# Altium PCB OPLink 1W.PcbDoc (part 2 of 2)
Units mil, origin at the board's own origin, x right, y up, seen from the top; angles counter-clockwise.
Board outline 1023.62 x 1417.32 mil, 4 copper layers (Top Layer, PWR Layer, GND Layer, Bottom Layer), stack 89.2 mil thick; 64 components, 74 nets, 299 pads, 144 vias.
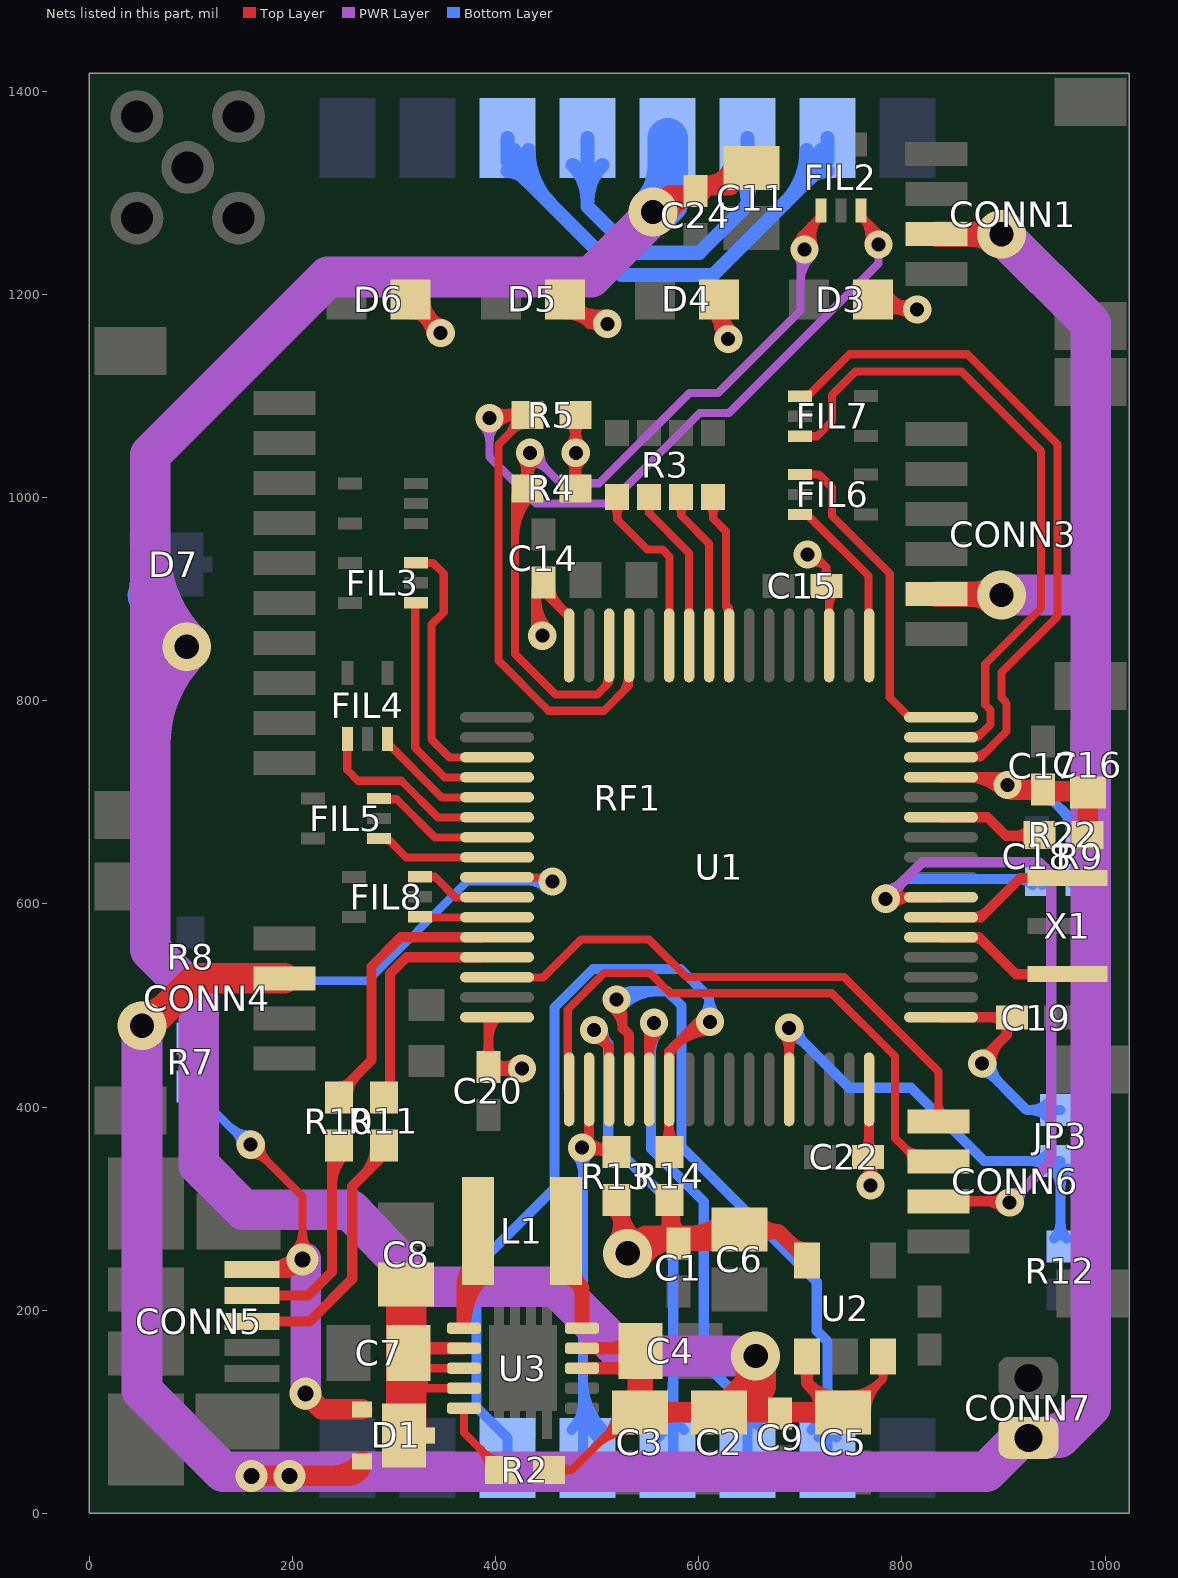
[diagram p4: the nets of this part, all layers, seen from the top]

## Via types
v1: diameter 27.8, hole 13.78, Top Layer to Bottom Layer, tented both sides, 127 vias
v2: diameter 48, hole 24, Top Layer to Bottom Layer, tented both sides, 8 vias
v3: diameter 31.5, hole 15.75, Top Layer to Bottom Layer, tented both sides, 4 vias
v4: diameter 25.98, hole 12, Top Layer to Bottom Layer, tented bottom, 4 vias
v5: diameter 26, hole 12, Top Layer to Bottom Layer, tented bottom, 1 vias

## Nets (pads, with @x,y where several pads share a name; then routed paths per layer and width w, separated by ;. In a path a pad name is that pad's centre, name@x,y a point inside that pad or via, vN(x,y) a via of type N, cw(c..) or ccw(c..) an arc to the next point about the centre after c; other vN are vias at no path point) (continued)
NetFIL2_1: FIL2.1 R4.1 U1.30 | length 1222
  Top Layer w8: 419,960.26 cw(c478.15,960.26) R4.1@436.32,1002.08 ; 419,979.57 cw(c458.84,979.57) R4.1@430.67,1007.74 ; R4.1@419,998.89 cw(c439.52,998.89) R4.1@425.01,1013.4 ; R4.1@424.46,1015.92 ccw(c407.77,1032.61) 431.38,1032.61 ccw(c454.99,1032.61) R4.1@438.29,1015.92 ; v1@425.7,1038.61 cw(c407.81,1027.02) R4.1@428.4,1021.5 ; v1@427,1037 cw(c416.44,1026.44) 431.38,1026.44 ; R4.1@428.48,1021.78 cw(c450.19,1015.96) v1@438.95,1035.43 ; R4.1@430.5,1007.5 419,996 419,846 458.91,806.09 500.09,806.09 511.73,817.73 U1.30@511.73,854.5 ; R4.1@431.38,1009 431.38,1041.38 v1(434,1044) ; R4.1@431.38,1013.78 cw(c464.22,1013.78) v1@441,1037 ; 505.72,811.72 ccw(c494.13,823.3) U1.30@510.52,823.3 ; v1@698.23,1242.02 cw(c713.97,1247.43) 702.2,1259.2 ; v1@699.11,1252.61 ccw(c694.35,1261) 704,1261 ; v1(704,1244) 704,1261 ; v1@705.79,1244.62 cw(c727.45,1252.06) 711.26,1268.26 ; v1@708.89,1252.61 cw(c713.65,1261) 704,1261 ; v1@713.36,1247.22 cw(c740.93,1256.7) FIL2.1@720.31,1277.31 ; FIL2.1@715.87,1272.87 cw(c720.32,1268.42) FIL2.1@720.32,1274.71 ; FIL2.1@720.32,1282.52 FIL2.1@720.32,1277.32 ; 704,1261 FIL2.1@720.32,1277.32
  PWR Layer w8: v1@434,1034.1 cw(c434,1010.21) 450.9,1027.1 cw(c467.79,1044) v1@443.9,1044 ; v1(434,1044) 464,1014 502,1014 591,1103 619,1103 700,1184 700,1249 v1@699,1250 ; v1@697,1237 cw(c689.76,1229.76) 700,1229.76 cw(c718.24,1229.76) v1@705.34,1242.66 ; 700,1210.45 cw(c737.55,1210.45) v1@711,1237
NetFIL2_3: FIL2.3 R5.1 U1.29 | length 1343
  Top Layer w8: v1(394,1078) 397,1081 R5.1@431.38,1081 ; v1@398.99,1086.55 ccw(c411.11,1107.34) R5.1@417.34,1084.09 ; v1@401,1071 cw(c425.14,1046.86) R5.1@425.14,1081 ; v1@401,1085 ccw(c410.65,1094.65) 410.65,1081 ; v1@402.57,1073.05 cw(c422.8,1061.37) R5.1@416.76,1083.94 ; 410.88,1059.88 ccw(c389.77,1081) R5.1@419.63,1081 ; 417.14,1066.14 cw(c429.41,1053.87) R5.1@429.41,1071.22 ; R5.1@422.49,1074.08 ccw(c405.8,1057.39) 405.8,1081 ccw(c405.8,1104.61) R5.1@422.49,1087.92 ; R5.1@431,1080 403,1052 403,839.37 452.29,790.09 506.71,790.09 531.42,814.79 U1.29@531.42,854.5 ; 523.32,806.69 ccw(c506.71,823.3) U1.29@530.2,823.3 ; FIL2.3@759.68,1274.71 cw(c759.68,1268.42) FIL2.3@764.13,1272.87 ; FIL2.3@759.68,1282.52 FIL2.3@759.68,1277.32 ; v1@767.33,1251.13 ccw(c739.61,1257.24) FIL2.3@759.69,1277.31 ; 770.01,1266.99 cw(c756.53,1253.51) v1@775.15,1249.41 ; v1(777,1249) 777,1260 FIL2.3@759.68,1277.32
  PWR Layer w8: v1@387,1071 cw(c370.11,1054.11) 394,1054.11 cw(c417.89,1054.11) v1@401,1071 ; v1(394,1078) 394,1040 440,994 512,994 601,1083 629.72,1083 777,1230.28 777,1239 v1@783,1245
NetFIL6_1: FIL6.1 U1.16 | length 325.9
  Top Layer w8: FIL6.1@699.52,1022.68 718.32,1022.68 731,1010 731,982 788,925 788,803 807.36,783.64 U1.16@838.5,783.64
NetFIL6_3: FIL6.3 U1.17 | length 161.2
  Top Layer w8: FIL6.3@699.52,983.32 706.68,983.32 767,923 767,855.14 U1.17@767.64,854.5
NetFIL7_1: FIL7.1 U1.14 | length 709.4
  Top Layer w8: FIL7.1@699.52,1099.68 707.17,1099.68 748.48,1141 864.38,1141 953,1052.38 953,883 898,828 898,803 902,799 ; FIL7.1@705.82,1101.2 ccw(c705.82,1108.1) FIL7.1@710.7,1103.22 ; U1.14@838.5,744.27 877.31,744.27 903,769.96 903,797 ; U1.14@869.7,745.48 ccw(c869.7,766.78) 884.76,751.72
NetFIL7_3: FIL7.3 U1.15 | length 670.3
  Top Layer w8: FIL7.3@699.52,1060.32 716.32,1060.32 731,1075 731,1100.89 754.11,1124 858.75,1124 937,1045.75 937,891 882,836 882,796 887,791 887,776.59 874.37,763.95 U1.15@838.5,763.95 ; U1.15@869.7,765.17 ccw(c869.7,779.36) 879.74,769.33
NetJP3_1: JP3.1 R12.1 U1.60 | length 637.5
  Top Layer w10: v1@682.71,471.71 cw(c667.52,456.52) 689,456.52 cw(c710.48,456.52) v1@695.29,471.71 ; U1.60@688.9,417.5 689,417.6 v1(689,478)
  Bottom Layer w10: v1@689,469.1 cw(c689,447.62) 704.19,462.81 cw(c719.38,478) v1@697.9,478 ; v1(689,478) 748,419 809,419 881,347 JP3.1@956,347 R12.1@956,273.62 ; JP3.1@944.15,339.4 ccw(c925.8,321.05) 925.8,347 ccw(c925.8,372.95) JP3.1@944.15,354.6 ; JP3.1@948.4,339.4 cw(c930.05,321.05) 956,321.05 cw(c981.95,321.05) JP3.1@963.6,339.4 ; R12.1@949.79,270.8 ccw(c934.8,285.79) 956,285.79 ccw(c977.2,285.79) R12.1@962.21,270.8
NetL1_1: L1.1 U3.1 | length 151.4
  Top Layer w15: U3.1@368.93,185 368.93,223.93 ; U3.1@368.93,187.46 cw(c435.83,187.46) L1.1@388.53,234.77 ; 368.93,223.67 cw(c399.62,223.67) L1.1@377.92,245.37 ; L1.1@374.49,239.71 cw(c355.23,237.63) 368.93,223.93 ; L1.1@382,237 368.93,223.93
NetL1_2: L1.2 U3.10 | length 99.7
  Top Layer w15: L1.2@469.16,232.35 cw(c468.88,216.16) 485.07,216.16 ; L1.2@473,234 485.07,221.93 ; L1.2@477.55,240.47 ccw(c503.22,240.08) 485.07,221.93 ; U3.10@485.07,185 485.07,221.93
NetR3_1: R3.1 U1.27 | length 206
  Top Layer w8: R3.1@514.23,994 cw(c500.9,980.66) 519.76,980.66 cw(c538.61,980.66) R3.1@525.28,994 ; R3.1@519.76,1000.5 519.76,978.24 549.28,948.72 564.28,948.72 571.31,941.69 571.31,855.02 U1.27@570.79,854.5
NetR3_2: R3.2 U1.26 | length 181.8
  Top Layer w8: R3.2@546.85,993.06 cw(c541.19,984.75) 551.25,984.75 ; R3.2@551.25,1000.5 551.25,984.75 ; R3.2@555.65,993.06 ccw(c561.31,984.75) 551.25,984.75 ; U1.26@590.47,854.5 590.47,945.53 551.25,984.75
NetR3_3: R3.3 U1.25 | length 183.1
  Top Layer w8: R3.3@577.59,993.65 cw(c567.57,982.25) 582.75,982.25 ; R3.3@582.75,1000.5 582.75,982.25 ; R3.3@587.91,993.65 ccw(c597.93,982.25) 582.75,982.25 ; U1.25@610.16,854.5 610.16,954.84 582.75,982.25
NetR3_4: R3.4 U1.24 | length 209
  Top Layer w8: R3.4@608.72,994 cw(c595.39,980.66) 614.24,980.66 cw(c633.1,980.66) R3.4@619.77,994 ; R3.4@614.24,1000.5 614.24,979.38 627,966.63 627,894 ; 627,895.5 ccw(c639.64,895.5) U1.24@630.7,886.56 ; U1.24@628.7,886.13 ccw(c621.74,888.74) 627,894 ; U1.24@629.84,854.5 629.84,891.16 627,894 ; U1.24@630.59,886.67 cw(c636.29,894) 627,894
NetR13_1: R13.1 RF1.13 U1.50 | length 654.2
  Top Layer w10: v1@485,355 v1@490,360 ; v1(485,360) v1@490,360 ; v1@491.2,353.62 cw(c500.3,344.27) 503.67,356.87 ; v1@491.29,353.71 cw(c506.48,338.52) 506.48,360 cw(c506.48,381.48) v1@491.29,366.29 ; v1@491.99,360 cw(c491.99,330.58) R13.1@512.79,351.38 ; U1.50@492.05,417.5 492.05,362.05 v1@490,360 ; v1@492.71,364.45 ccw(c505.96,372.1) 502,357.32 ; 503.62,360 ccw(c503.62,372.97) R13.1@512.79,363.8 ; R13.1@516.64,355.62 512.27,360 v1@490,360
  Bottom Layer w10: RF1.13@474.68,82.16 ccw(c447.35,109.49) 486,109.49 ; v1@478.71,353.71 cw(c461.11,336.11) 486,336.11 ; 486,107.7 ccw(c532.13,107.7) RF1.13@499.51,75.09 ; 486,131.84 ccw(c556.27,131.84) RF1.13@506.58,82.16 ; 486,340.93 cw(c504.07,340.93) v1@491.29,353.71 ; v1@486,357 486,54.39 RF1.13@490.63,54.39
NetR14_1: R14.1 RF1.14 U1.54 | length 979.4
  Top Layer w10: R14.1@564.79,363.8 ccw(c550.32,378.27) 570.79,378.27 ; 570.79,379.3 ccw(c592.71,379.3) R14.1@577.21,363.8 ; R14.1@571,355.62 570.79,355.83 U1.54@570.79,417.5 570.79,454.79 600,484 v1(611,484) ; U1.54@571,448.7 cw(c586.23,448.7) 575.46,459.46 ; 577.03,461.03 cw(c611,427.07) v1@611,475.1 ; 594.1,478.1 cw(c611,461.21) v1@611,485.1
  Bottom Layer w10: RF1.14@411.89,54.39 411.89,74.11 381.32,104.67 381.32,243.32 458,320 458,498 496,536 582,536 610,508 610,484 v1(611,484) ; v1@604.71,490.29 ccw(c591.93,503.07) 610,503.07 ; 610,507.89 ccw(c634.89,507.89) v1@617.29,490.29
NetR22_2: R22.2 U1.11 | length 142.3
  Top Layer w10: U1.11@838.5,685.21 884.22,685.21 902.43,667 R22.2@940,667 ; 909.8,667 ccw(c909.8,691.61) R22.2@927.2,674.21 ; 914.63,667 cw(c914.63,649.22) R22.2@927.2,661.79
NetRF1_3: RF1.3 RF1.7 | length 672.3
  Bottom Layer w14: RF1.3@411.89,1321.24 cw(c411.89,1297.4) RF1.3@428.75,1314.25 ; RF1.3@411.89,1353.61 411.89,1331.11 524,1219 614,1219 726.85,1331.85 RF1.7@726.85,1353.61 ; RF1.3@418.45,1341.8 ccw(c460.08,1341.8) 430.64,1312.36 ; RF1.3@432.45,1341.8 ccw(c507.88,1341.8) 454.54,1288.46 ; 684.72,1289.72 ccw(c632.65,1341.8) RF1.7@706.29,1341.8 ; 708.62,1313.62 ccw(c680.45,1341.8) RF1.7@720.29,1341.8 ; 708.73,1313.73 cw(c726.85,1295.61) RF1.7@726.85,1321.24
NetRF1_4: RF1.4 RF1.6 | length 484.3
  Bottom Layer w14: RF1.4@476.09,1327.26 cw(c441,1292.16) 490.63,1292.16 cw(c540.26,1292.16) RF1.4@505.17,1327.26 ; RF1.4@490.63,1353.61 490.63,1286.48 536.11,1241 600.89,1241 648.11,1288.22 RF1.6@648.11,1353.61 ; RF1.6@633.57,1327.26 cw(c598.48,1292.16) 648.11,1292.16 cw(c697.74,1292.16) RF1.6@662.65,1327.26
NetRF1_10: RF1.10 U1.52 | length 901
  Top Layer w10: v1@513.89,498.71 cw(c498.93,477.37) 525,477.37 ; v1@518.28,497.13 cw(c517.69,489.84) 525,489.84 ; v1(519,506) 519,497 525,491 525,478 531.42,471.58 U1.52@531.42,417.5
  Bottom Layer w10: v1@518.22,506.78 cw(c535.65,489.35) 535.65,514 ; v1@524.15,513.25 ccw(c528.13,518.86) 533,514 ; v1@525.29,499.71 cw(c559.79,465.21) 559.79,514 ; v1@526,507 533,514 ; RF1.10@710.9,82.16 ccw(c672.39,120.67) 726.85,120.67 ccw(c781.31,120.67) RF1.10@742.8,82.16 ; RF1.10@717.97,75.09 ccw(c696.53,96.52) 726.85,96.52 ccw(c757.17,96.52) RF1.10@735.73,75.09 ; RF1.10@726.85,54.39 726.85,169.11 716.1,179.86 716.1,227.9 583,361 583,500 569,514 533,514
NetRF1_11: RF1.11 U1.53 | length 641.1
  Top Layer w10: U1.53@551.1,417.5 551.1,478.1 v1(556,483) ; U1.53@551.1,449.7 cw(c589.3,449.7) v1@562.29,476.71
  Bottom Layer w10: v1@549.71,476.71 cw(c541.76,468.76) 553,468.76 ; 553,454.28 cw(c584.72,454.28) v1@562.29,476.71 ; v1@553,476 553,359 605,307 605,149 648.11,105.89 ; RF1.11@636.57,85.59 ccw(c624.49,105.89) 648.11,105.89 ; RF1.11@648.11,54.39 648.11,105.89 ; RF1.11@659.65,85.59 cw(c671.73,105.89) 648.11,105.89
NetRF1_12: RF1.12 U1.51 | length 705.2
  Top Layer w10: v1@497,467.1 cw(c497,450.45) 508.77,462.23 ; v1@502,478 502,469 511.73,459.27 ; v1@505.87,475.27 ccw(c526.06,473.59) 511.73,459.27 ; U1.51@511.73,417.5 511.73,459.27
  Bottom Layer w10: v1@497.53,467.12 cw(c498.57,449.57) 511,462 ; v1@502,478 502,471 511,462 ; v1@505.88,475.47 ccw(c523.43,474.43) 511,462 ; RF1.12@553.42,82.16 ccw(c501.56,134.01) 574.9,134.01 ; RF1.12@560.49,75.09 ccw(c525.71,109.87) 574.9,109.87 ; RF1.12@569.37,54.39 574.9,59.92 574.9,303.1 511,367 511,462 ; 574.9,107.32 ccw(c610.49,107.32) RF1.12@585.32,82.16
  other v1: 497,476
NRST: C18.2 CONN6.2 R9.1 U1.7 | length 1126.1
  Top Layer w10: v1(784,605) 785.47,606.47 U1.7@838.5,606.47 ; v1@790.29,598.71 cw(c809.04,579.96) U1.7@809.04,606.47 ; v1@790.29,611.29 ccw(c801.93,622.93) 801.93,606.47 ; CONN6.2@835.9,307.32 904.68,307.32 v1(906,306) ; CONN6.2@859.41,302.5 cw(c871.04,290.87) 871.04,307.32 cw(c871.04,323.76) CONN6.2@859.41,312.13 ; 881.34,307.32 cw(c881.34,281.34) v1@899.71,299.71 ; 887.69,307.32 ccw(c887.69,324.31) v1@899.71,312.29
  PWR Layer w10: v1(784,605) 820,641 935,641 946.9,629.1 946.9,346.9 v1(906,306) ; v1@784,613.9 ccw(c784,635.38) 799.19,620.19 ccw(c814.38,605) v1@792.9,605 ; v1@906,314.9 ccw(c906,336.38) 921.19,321.19 ccw(c936.38,306) v1@914.9,306
  Bottom Layer w10: v1(784,605) 803.38,624.38 R9.1@974,624.38 ; v1@784,613.9 ccw(c784,635.38) 799.19,620.19 ccw(c814.38,605) v1@792.9,605 ; 914.14,624.38 cw(c914.14,604.52) C18.2@928.18,618.56 ; 918.97,624.38 ccw(c918.97,637.41) C18.2@928.18,628.19 ; C18.2@937.82,618.56 cw(c951.86,604.52) 951.86,624.38 ; C18.2@937.82,628.19 ccw(c947.03,637.41) 947.03,624.38 ; 951.47,624.38 ccw(c951.47,648.88) R9.1@968.79,631.55 ; 956.14,624.38 cw(c956.14,606.49) R9.1@968.79,619.14
OSC_IN: U1.5 X1.1 | length 153.7
  Top Layer w10: U1.5@838.5,567.1 875.9,567.1 912.24,530.76 X1.1@965,530.76 ; U1.5@869.7,566.89 cw(c869.7,551.41) 880.65,562.35
OSC_OUT: U1.6 X1.2 | length 158.2
  Top Layer w10: U1.6@838.5,586.79 877.79,586.79 916.24,625.24 X1.2@965,625.24 ; U1.6@869.7,587 ccw(c869.7,607.04) 883.87,592.87
PG: R2.2 U3.5 | length 112.8
  Top Layer w8: U3.5@368.93,103.63 368.93,79.45 R2.2@405.38,43 ; 385.32,63.06 cw(c365.27,43) R2.2@393.63,43 ; 390.08,58.3 ccw(c403.41,71.64) R2.2@403.41,52.78
S1_IN: FIL3.3 U1.35 | length 271.8
  Top Layer w8: FIL3.3@321.48,935.68 338.32,935.68 349,925 349,887 337,875 337,762 354.73,744.27 U1.35@401.5,744.27
S2_IN: FIL3.1 U1.36 | length 233.9
  Top Layer w8: FIL3.1@321,895 321,753.63 350.04,724.58 U1.36@401.5,724.58
S3_IN: FIL4.3 U1.37 | length 137
  Top Layer w8: FIL4.3@293.5,758.5 347.1,704.9 U1.37@401.5,704.9 ; FIL4.3@293.68,754.71 cw(c293.68,746) 299.84,752.16
S4_IN: FIL4.1 U1.38 | length 192.7
  Top Layer w8: FIL4.1@254,757.83 254,732 264.8,721.2 307.2,721.2 343.19,685.21 U1.38@401.5,685.21
S5_IN: FIL5.3 U1.39 | length 137
  Top Layer w8: FIL5.3@280,703 302.77,703 340.25,665.53 U1.39@401.5,665.53
S6_IN: FIL5.1 U1.40 | length 129.3
  Top Layer w8: FIL5.1@287,666 292,666 312.16,645.84 U1.40@401.5,645.84 ; FIL5.1@291.78,662.8 cw(c291.78,654.55) 297.61,660.39
SWDCLK: CONN6.3 U1.49 | length 617.8
  Top Layer w8: 471.1,454.68 ccw(c478.34,454.68) U1.49@473.22,449.56 ; U1.49@472.36,417.5 471.1,418.76 471.1,496.1 506.9,531.9 552.1,531.9 572,512 731,512 793,450 793,369.66 815.97,346.68 CONN6.3@835.9,346.68 ; 801.78,360.88 ccw(c817.2,376.3) CONN6.3@817.2,354.5 ; 804.73,357.93 cw(c793.48,346.68) CONN6.3@809.39,346.68
SWDIO: CONN6.4 U1.46 | length 582.3
  Top Layer w8: U1.46@401.5,527.73 446.73,527.73 484,565 551,565 588,528 743,528 835.9,435.1 CONN6.4@835.9,386.06 ; CONN6.4@830.37,391.58 ccw(c817.04,404.91) 835.9,404.91 ccw(c854.76,404.91) CONN6.4@841.42,391.58
TO_REG: C7.1 C8.1 D1.3 U3.2 U3.3 U3.4 | length 326.1
  Top Layer w8: C7.1@314.53,158 C7.1@329.53,143 ; U3.4@368.93,123.32 329.53,123.32 C7.1@329.53,143 ; U3.3@368.93,143 C7.1@329.53,143
  Top Layer w12: C7.1@312,163 312.31,162.68 U3.2@368.93,162.68
  Top Layer w40: D1.3@310,77 312,79 312,163 C8.1@312,225.47
UART1_RX: FIL8.1 U1.43 | length 76.2
  Top Layer w8: FIL8.1@325.48,587.32 326.01,586.79 U1.43@401.5,586.79
UART1_TX: FIL8.3 U1.42 | length 84.4
  Top Layer w8: FIL8.3@325.48,626.68 340.32,626.68 360.53,606.47 U1.42@401.5,606.47
USB_D_N: R10.1 U1.44 | length 294.8
  Top Layer w10: R10.1@245,411 247,413 247,415 278,446 278,538.46 306.65,567.1 U1.44@386.5,567.1 ; R10.1@246,420.37 ccw(c246,435.75) R10.1@256.87,424.87 ; R10.1@254.78,411.59 cw(c281.79,411.59) 262.69,430.69
USB_D_P: R11.1 U1.45 | length 221.3
  Top Layer w10: R11.1@296,407 296,531 312.42,547.42 U1.45@386.5,547.42
USB_PWR: CONN5.1 D1.2 R7.1 | length 682.6
  Top Layer w8: v1@159,353.1 cw(c159,329.21) 175.9,346.1 cw(c192.79,363) v1@168.9,363 ; v1(159,363) 210,312 v3(210,250) ; v3@201.69,258.31 ccw(c181.64,278.36) 210,278.36 ccw(c238.36,278.36) v3@218.31,258.31
  Top Layer w17: CONN5.1@160.33,240.18 195.18,240.18 ; CONN5.1@179.13,240.05 ccw(c179.13,278.47) v3@206.3,251.3 ; 190.56,242.22 cw(c200,225.88) v3@207.22,243.3 ; v3@207.5,252.5 195.18,240.18 ; v3@207.7,243.13 ccw(c203.82,231.54) 195.18,240.18
  Top Layer w20: v3(213,118) 228.41,102.59 D1.2@268.66,102.59
  PWR Layer w30: v3@213,117 v3(213,118) v3@213,251
  Bottom Layer w8: R7.1@100,408.63 cw(c100,383.59) 117.7,401.3 ; R7.1@109.78,418.41 ccw(c131.96,418.41) 116.28,402.72 ; R7.1@110,423.38 110,409 156,363 v1(159,363) ; 136.98,382.02 ccw(c159,404.04) v1@159,372.9 ; 144.23,374.77 cw(c132.45,363) v1@149.1,363
USB_R_N: CONN5.2 R10.2 | length 258.2
  Top Layer w10: CONN5.2@160.33,214.59 215.59,214.59 239,238 R10.2@239,356 ; 239,322.31 cw(c284.1,322.31) R10.2@252.21,354.2 ; 239,346.46 cw(c259.95,346.46) R10.2@245.14,361.27
USB_R_P: CONN5.3 R11.2 | length 292.8
  Top Layer w10: CONN5.3@160.33,189 217,189 259,231 259,322 296.5,359.5 R11.2@296.5,361.5 ; 269.77,332.77 ccw(c242.14,360.41) R11.2@281.22,360.41
VBUS_SEN: R7.2 R8.2 U1.41 | length 659.4
  Top Layer w8: U1.41@401.5,626.16 451.84,626.16 v1(456,622)
  Bottom Layer w8: R7.2@93.08,476.51 ccw(c76.39,493.2) 100,493.2 ccw(c123.61,493.2) R7.2@106.92,476.51 ; R8.2@93.08,515.49 cw(c76.39,498.8) 100,498.8 cw(c123.61,498.8) R8.2@106.92,515.49 ; R8.2@106.92,517.46 cw(c123.61,500.77) 123.61,524.38 cw(c123.61,547.99) R8.2@106.92,531.29 ; R7.2@110,470.62 100,480.62 R8.2@100,524.38 274.38,524.38 372,622 v1(456,622) ; v1@449,615 ccw(c432.11,598.11) 432.11,622 ccw(c432.11,645.89) v1@449,629
VCC: C1.1 C6.1 C14.1 C15.2 C16.2 C17.1 C19.2 C20.1 C22.1 D3.2 D4.2 D5.2 D6.2 JP3.2 R4.2 R5.2 R9.2 R13.2 R14.2 R22.1 U1.1 U1.13 U1.19 U1.32 U1.48 U1.64 U2.5 | length 3229
  Top Layer w8: v1(707,944) 713,944 725.62,931.38 ; v1@710.42,934.71 cw(c715.42,921.17) 725.62,931.38 ; v1@716.9,944 ccw(c726.31,944) 719.65,937.35 ; C15.2@720.2,918.62 ccw(c707.91,931.38) 725.62,931.38 ; C15.2@724.04,907.48 cw(c713.82,897.26) 728.27,897.26 ; C15.2@725.62,913 725.62,931.38 ; U1.19@728.27,854.5 C15.2@728.27,913 ; 728.27,891.02 cw(c751.53,891.02) C15.2@735.08,907.48 ; C15.2@731.04,918.62 cw(c743.33,931.38) 725.62,931.38
  Top Layer w10: D6.2@316.5,1180.31 cw(c316.5,1144.86) 341.56,1169.93 cw(c366.63,1195) D6.2@331.18,1195 ; D6.2@316.5,1195 v1@348.75,1162.75 ; D6.2@323.35,1180.45 cw(c309.06,1155.7) v1@337.23,1160.5 ; D6.2@328.34,1183.16 cw(c307.18,1162) v1@337.1,1162 ; D6.2@335.22,1180.93 cw(c316.25,1169.97) v1@337.41,1164.3 ; D6.2@335.52,1180.4 ccw(c353.75,1190.93) v1@348.3,1170.59 ; 336.78,1174.72 ccw(c346,1183.94) v1@346,1170.9 ; C20.1@388.18,448.38 ccw(c376.56,460) 393,460 ccw(c409.44,460) C20.1@397.82,448.38 ; C20.1@393,439.62 U1.48@393,488 ; 393,467.33 cw(c422.53,467.33) U1.48@401.65,488.21 ; v1@440,860 440,909.38 C14.1@447,916.38 447,908.59 472.36,883.23 U1.32@472.36,854.5 ; 440,899.97 ccw(c481.97,899.97) v1@452.29,870.29 ; C14.1@453.81,912.44 ccw(c479.55,912.44) 461.35,894.24 ; D5.2@468.62,1180.32 cw(c469.62,1148.46) 492.16,1171 ; R4.2@472.41,1015.21 ccw(c457.43,1030.2) 478.62,1030.2 ccw(c499.82,1030.2) R4.2@484.83,1015.21 ; R5.2@472.41,1074.79 cw(c457.43,1059.8) 478.62,1059.8 cw(c499.82,1059.8) R5.2@484.83,1074.79 ; v1@472.71,1037.71 cw(c458.43,1023.43) 478.62,1023.43 ; v1@472.71,1050.29 ccw(c458.43,1064.57) 478.62,1064.57 ; v1@473.33,1037.14 cw(c465.8,1028.03) 477.22,1024.97 ; 478.54,1029.9 cw(c488.71,1027.18) v1@483.45,1036.29 ; R4.2@478.62,1009 R5.2@478.62,1081 ; R4.2@478.62,1021.61 cw(c501.39,1021.61) v1@485.29,1037.71 ; 478.62,1066.39 ccw(c501.39,1066.39) v1@485.29,1050.29 ; 479.7,1026.19 cw(c488.68,1028.59) v1@483.73,1036.47 ; D5.2@482.84,1194.54 ccw(c514.7,1193.54) 492.16,1171 ; D5.2@483.47,1179.7 ccw(c507.38,1203.6) v1@510.09,1169.9 ; v1@502.89,1165.65 ccw(c492.16,1157.57) 492.16,1171 ; v1@502.89,1176.35 cw(c492.16,1184.43) 492.16,1171 ; v1@509.29,1179.87 cw(c505.1,1231.93) D5.2@468.16,1195 492.16,1171 ; v1(510,1171) 492.16,1171 ; R13.2@512.79,300.2 cw(c480.91,268.31) v2@526,268.31 ; v2@514.86,267.47 ccw(c492.21,284.64) 519.66,291.99 ccw(c545.22,298.84) v2@536.36,273.9 ; v2@516.56,269.44 ccw(c493.79,292.21) 526,292.21 ; R13.2@519,308.38 526,301.38 v2@526,262 ; R13.2@519.86,307.27 cw(c505.05,292.46) 526,292.46 ; 526,281.65 ccw(c548.8,281.65) v2@535.32,263.26 ; R13.2@526,301.38 ccw(c563.26,301.38) v2@541.23,271.32 ; D4.2@611.6,1182.84 cw(c600.87,1167) 620,1167 ; D4.2@617.38,1176.78 ccw(c633.36,1181.06) v1@630.52,1164.77 ; D4.2@619.83,1195 D4.2@620,1194.83 ; 620,1173.13 ccw(c643.64,1173.13) v1@628.28,1155.16 ; v1@621.09,1160.07 ccw(c615.79,1162.79) 620,1167 ; v1@627.34,1164.74 cw(c625.8,1172.8) 620,1167 ; D4.2@628.29,1183 ccw(c639.58,1167) 620,1167 ; v1@632,1155 620,1167 ; v1@634.78,1162.77 cw(c662.17,1194.83) D4.2@620,1194.83 ; C22.1@761.81,355.82 ccw(c747.73,369.9) 767.64,369.9 ; v1@762.71,329.29 ccw(c747.52,344.48) 769,344.48 ccw(c790.48,344.48) v1@775.29,329.29 ; v1@765.02,330.96 ccw(c759.85,341.29) 771.01,338.3 ccw(c778.05,336.42) v1@773.97,330.38 ; C22.1@765.74,346.18 cw(c757.88,338.32) 769,338.32 ; 767.64,364.99 ccw(c780.61,364.99) C22.1@771.44,355.82 ; U1.64@767.64,417.5 767.64,356.98 769.62,355 769,354.38 v1(769,323) ; v1@769,330.79 cw(c790.77,330.79) C22.1@775.38,346.18 ; D3.2@771.5,1195 781.5,1185 v1(815,1185) cw(c815,1220.99) D3.2@784.1,1202.53 ; D3.2@775.52,1197.4 ccw(c797.38,1210.46) 797.38,1185 ; v1@806.87,1181.39 ccw(c793.11,1175.28) 797,1189.82 ccw(c800.9,1204.36) v1@809.76,1192.19 ; v1@808.71,1178.71 ccw(c793.52,1163.52) 793.52,1185 ccw(c793.52,1206.48) v1@808.71,1191.29 ; U1.1@838.5,488.36 911.74,488.36 913.38,490 906.1,490 903.1,487 903.1,471.1 884,452 v1@884,445 ; U1.13@838.5,724.58 900.42,724.58 v1@903.38,721.62 ; U1.13@864.21,724.58 cw(c864.21,677.21) v1@897.71,710.71 ; v1@879,451.9 ccw(c879,463.72) 887.36,455.36 ; 887.12,488.36 cw(c887.12,470.68) 899.62,483.18 cw(c891.23,474.79) 903.1,474.79 ; v1@887.9,443 cw(c919.04,443) 897.02,465.02 ; 888.36,724.58 cw(c888.36,701.36) v1@904.78,717.78 ; 888.87,488.36 ccw(c888.87,503.57) C19.2@899.62,492.82 ; 903.1,471.05 cw(c917.99,471.05) C19.2@908.69,482.68 ; C17.1@939,708 C17.1@945,702 ; 620,1167 D4.2@620,1194.83
  Top Layer w15: C20.1@393,439.62 394.62,438 v1(426,438) ; C20.1@396.05,442.67 ccw(c407.32,453.95) 407.32,438 ; v1@421.48,433.48 ccw(c410.55,422.55) 410.55,438 ccw(c410.55,453.45) v1@421.48,442.52 ; R14.2@566.56,301.97 cw(c555.84,291.25) 571,291.25 cw(c586.16,291.25) R14.2@575.44,301.97 ; R14.2@571,301.69 ccw(c612.14,301.69) C1.1@583.05,272.61 ; R14.2@571,308.38 571,276.62 576.62,271 C1.1@580,267.62 ; 574.51,288.6 cw(c593.18,293.61) R14.2@576.44,303.27 ; C6.1@640,277.53 678.32,277.53 ; C6.1@655.91,269.52 cw(c675.25,250.19) 675.25,277.53 ; C6.1@657.21,288.05 ccw(c678.31,303.96) 678.31,277.53 ; 689.16,266.68 ccw(c706.6,284.13) U2.5@706.6,259.46 ; U2.5@706.6,249.24 678.32,277.53
  Top Layer w20: v1(904,717) 908.62,712.38 C17.1@939,712.38 ; v1@906.76,719.76 ccw(c924.57,737.57) 924.57,712.38 ; C17.1@938,711 C17.1@940,709 ; C17.1@940,712 941,711 C16.2@972.44,711 ; R22.1@982.62,668 983,668.38 C16.2@983,709.44
  Top Layer w25: v2@532.5,255.5 548,271 C1.1@576.62,271 ; v2@539.88,250.12 cw(c576.62,228.24) C1.1@576.62,271 ; C1.1@591.41,271 ccw(c591.41,322.21) C6.1@627.62,286 ; C6.1@640,277.53 633.47,271 C1.1@576.62,271
  Bottom Layer w10: v1@879,434.1 cw(c879,417.54) 890.71,429.25 ; v1(879,443) 879,440.96 922.96,397 JP3.2@956,397 ; v1@887.9,443 ccw(c914.3,443) 895.63,424.33 ; v1(904,717) 933,717 979.38,670.62 R9.2@980,670.62 ; v1@910.29,710.71 cw(c925.48,695.52) 925.48,717 cw(c925.48,738.48) v1@910.29,723.29 ; JP3.2@944.15,389.4 ccw(c925.8,371.05) 925.8,397 ccw(c925.8,422.95) JP3.2@944.15,404.6 ; 958.31,691.69 cw(c939.21,672.59) R9.2@966.22,672.59 ; R9.2@964.13,685.87 ccw(c975,696.75) R9.2@975,681.37
  other v1: 446,864 479,1044 629,1156 346,1162
  other v2: 530,256
VCC_5V: C2.1 C3.1 C4.1 C5.1 C9.1 C11.1 C24.2 D7.2 R2.1 RF1.5 U2.1 U2.3 U3.8 U3.9 | length 3785.1
  Top Layer w8: R2.1@452.62,43 475,43 ; R2.1@462.21,36.87 cw(c475,26.59) 475,43 ; R2.1@462.21,49.13 ccw(c475,59.41) 475,43 ; 498.16,66.16 cw(c536.09,28.23) C3.1@536.09,81.87 ; 509.19,77.19 ccw(c486.85,99.53) C3.1@518.44,99.53 ; 511.82,79.82 cw(c536.09,55.54) C3.1@536.09,89.87 ; C3.1@542,99.53 531.53,99.53 475,43 ; C5.1@735.47,99.53 C5.1@742,99.53 748.53,99.53 781.4,132.4 ; C5.1@747.91,109.18 ccw(c747.91,133.99) C5.1@765.45,116.45 ; C5.1@747.91,117.18 ccw(c747.91,161.3) 779.1,130.1 ; C5.1@757.56,99.53 cw(c779.36,99.53) C5.1@763.95,114.95 ; C5.1@765.56,99.53 cw(c806.68,99.53) 777.6,128.6 ; U2.3@776.18,142.76 cw(c768.52,132.4) 781.4,132.4 ; U2.3@781.4,154.76 781.4,132.4 ; U2.3@786.63,142.76 ccw(c794.28,132.4) 781.4,132.4
  Top Layer w12: U3.8@485.07,143 525.47,143 C4.1@542.47,160 539.79,162.68 U3.9@485.07,162.68 ; 511.16,162.68 ccw(c511.16,191.31) C4.1@531.4,171.07 ; U2.1@701.79,145.03 cw(c690.19,133.43) 706.6,133.43 cw(c723,133.43) U2.1@711.4,145.03 ; U2.1@706.6,154.76 706.6,128.4 C5.1@735.47,99.53 ; 708.31,126.69 ccw(c736.09,154.47) C5.1@736.09,115.18 ; 709.81,125.19 cw(c684.15,99.53) C5.1@720.44,99.53
  Top Layer w20: C3.1@542,99.53 C2.1@620,99.53 C5.1@735.47,99.53 ; v2(555,1281) 571.62,1297.62 C24.2@599,1297.62 ; C3.1@556.15,91.29 cw(c576.04,71.39) 576.04,99.53 cw(c576.04,127.66) C3.1@556.15,107.77 ; v2@568.13,1276.14 cw(c599,1264.7) C24.2@599,1297.62 ; C11.1@634.82,1327.46 cw(c608.51,1334.32) C24.2@608.51,1307.13 ; C11.1@650,1326.53 630.6,1307.13 C24.2@608.5,1307.13 ; C5.1@727.85,91.29 ccw(c707.96,71.39) 707.96,99.53 ccw(c707.96,127.66) C5.1@727.85,107.77 ; C24.2@599,1297.62 C24.2@608.5,1307.13
  Top Layer w25: C3.1@535.53,106 ccw(c518.76,122.77) 542.47,122.77 ; C4.1@536,147.62 cw(c520.37,132) 542.47,132 cw(c564.57,132) C4.1@548.95,147.62 ; C3.1@542,99.53 542.47,100 C4.1@542.47,160
  Top Layer w40: C2.1@636.13,105.79 656,125.66 v2(656,155)
  PWR Layer w40: 60,756.43 cw(c192.57,756.43) v2@98.83,850.17 ; 60,949.57 ccw(c192.57,949.57) v2@98.83,855.83 ; v2@559,1282 494,1217 235,1217 60,1042 60,555 108,507 108,343 152,299 257,299 330,223 460,223 528,155 v2@637,155
  Bottom Layer w20: D7.2@49.66,908.41 49.66,897.34 51.35,895.65 ; 68.69,878.31 ccw(c96,905.63) v2@96,867 ; 73.51,873.49 cw(c53.03,853) v2@82,853 ; v2@79,868 62.5,884.5 61.89,884.5 51.35,895.05 ; 51.35,895.05 cw(c59.53,903.23) 49.85,909.58 ccw(c59.23,903.54) 51.35,895.65 ; 51.35,895.05 51.35,895.65
  Bottom Layer w40: v2@552.17,1283.83 ccw(c510.65,1325.35) RF1.5@569.37,1325.35 ; v2@555,1280 560,1280 569.37,1289.37 RF1.5@569.37,1353.61
  other v2: 96,853
VCC_UNREG: CONN1.2 CONN3.2 CONN4.2 CONN7.1 D1.1 | length 3239.8
  Top Layer w20: v3(160,37) v3(197,37) 254.25,37 ; 237.04,37 ccw(c237.04,81.06) D1.1@268.2,49.91 ; D1.1@268.66,51.41 254.25,37 ; D1.1@268.82,51.38 cw(c254.25,51.57) 254.25,37 ; CONN1.2@833.9,1259.32 CONN1.2@834.21,1259
  Top Layer w25: CONN3.2@833.9,904.94 897.06,904.94 v2(898,904) ; CONN1.2@834.21,1259 v2(898,1259) ; 867.96,904.94 cw(c867.96,873.96) v2@889.87,895.87 ; 872.52,904.94 ccw(c872.52,929.48) v2@889.87,912.13 ; v2@889.87,1250.87 ccw(c870.24,1231.24) 870.24,1259 ccw(c870.24,1286.76) v2@889.87,1267.13
  Top Layer w30: v2@52,474 104.68,526.68 CONN4.2@192.1,526.68 ; v2@52,489 ccw(c52,525.21) 77.61,499.61
  PWR Layer w40: v2@52,470 52,121 132,41 883,41 916.47,74.47 954.73,74.47 985.91,105.66 985.91,1171.09 v2(898,1259) ; v2(898,904) 984.91,904 ; CONN7.1@933.24,75.14 ccw(c933.24,128.63) 971.06,90.81
  other v2: 52,480
pads on no net: CONN1.0 CONN2.0 CONN3.0 CONN4.0 CONN5.4 CONN6.0 D7.1 U1.2 U1.3 U1.4 U1.8 U1.9 U1.10 U1.20 U1.21 U1.22 U1.55 U1.56 U1.57 U1.58 U1.59 U1.61 U1.62 U3.6

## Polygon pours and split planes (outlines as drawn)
VCC on PWR Layer "PWR Layer-VCC" (solid, remove dead copper, pour order 14): 60,0 970,0 970,1390 395,1390 395,1215 60,1215
GND on GND Layer "GND Layer-GND" (solid, remove dead copper, pour order 12): 0,0 1023.62,0 1023.62,1417.32 0,1417.32
GND on Top Layer "Top Layer-GND" (solid, remove dead copper, pour order 10): 0,0 1023.62,0 1023.62,1417.32 0,1417.32
GND on Bottom Layer "Bottom Layer-GND" (solid, remove dead copper, pour order 8): 0,0 1023.62,0 1023.62,1417.32 0,1417.32

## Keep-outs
Keep-Out Layer:
  the board outline again, w1

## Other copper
Top Layer:
  pour cut-out: 350,340 350,106 505,106 504,340

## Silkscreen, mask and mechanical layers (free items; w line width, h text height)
Top Overlay:
  text "OPLINK" at 205,1322 h110
  text "1W" at 480,1322 h110
  text "+" at 778,1282 h55
  text "10%" at 258,1128 h45
  text "25%" at 406,1128 h45
  text "75%" at 555,1128 h45
  text "90+%" at 701,1128 h45
  text "+" at 232,1036 h55
  text "+" at 778,1005 h55
  text "r" at 532,631 h200
  text "Fuck Yeah!" at 492,548 h70
  text "+" at 232,509 h55
  text "+" at 834,44 h90
Bottom Overlay:
  text "www.OpenPilot.org" at 946,791 h70 r270
Mechanical 15:
  lines w7: 605,1077.17 605,1287.17 815,1287.17 815,1077.17 605,1077.17
Mechanical 16:
  lines w10: 240,710 415,710 415,985 240,985 240,710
